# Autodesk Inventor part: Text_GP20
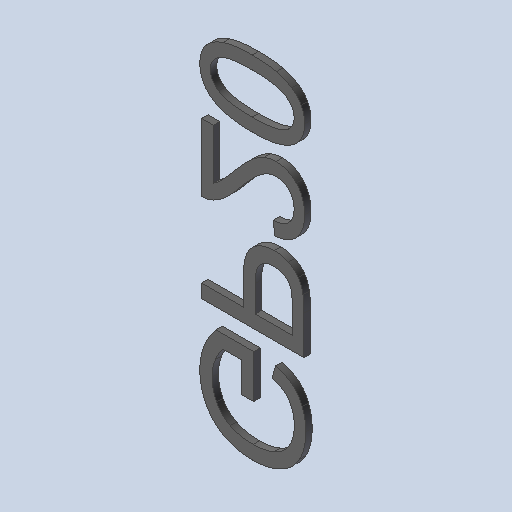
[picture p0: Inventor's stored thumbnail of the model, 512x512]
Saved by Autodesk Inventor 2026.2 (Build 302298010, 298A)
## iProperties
Created: 2026-10
Part Number: Text_GP20
Material: Générique
Document SubType Name: Modeling
Designer: mel
Density: 1 g/cm^3
Appearance: Par défaut
Author: mel
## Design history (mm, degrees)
feature "Base1"
feature "Base2"
feature "Base3"
feature "Base4"
node "Solide1"
node "Solide2"
node "Solide3"
node "Solide4"
